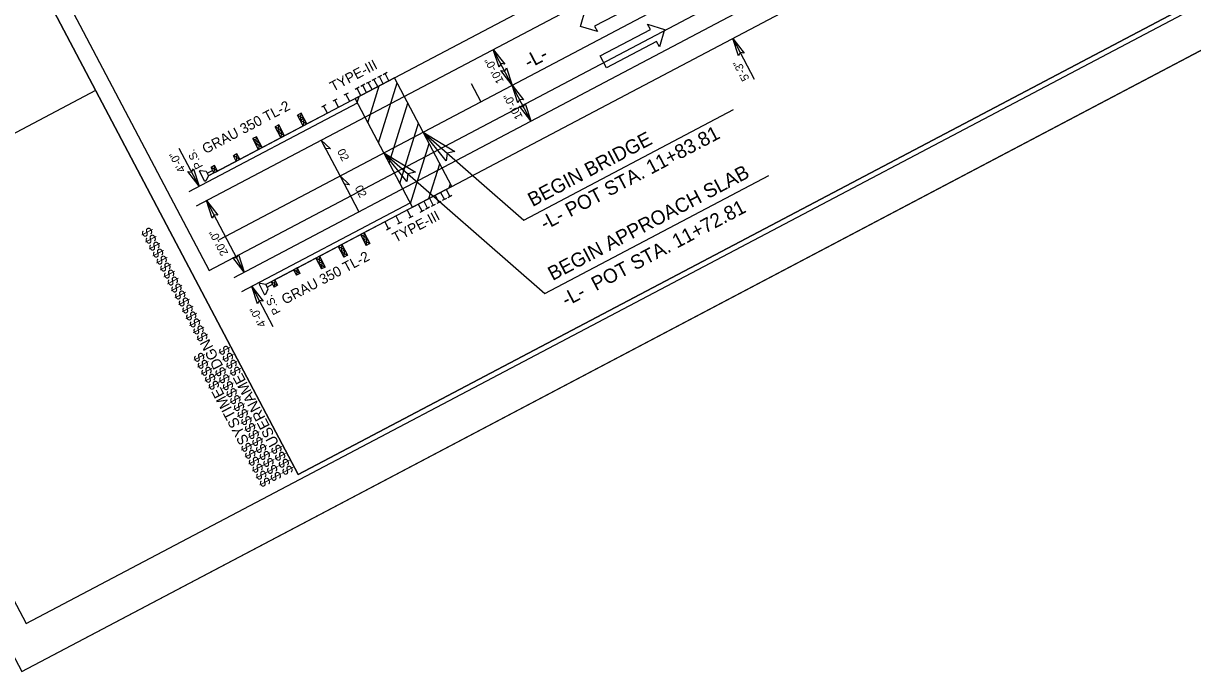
# Model space of a CAD drawing. Extents: x 1380651 to 1383136, y 594581 to 596344.
# Drawn here: x 1381162 to 1381741, y 594581 to 594902 of the extents above; entities that cross this region are included whole.
import ezdxf

# ---------------------------------------------------------------- set-up
doc = ezdxf.new("R2010")
doc.units = 0
for name, color, linetype in [('Default', 7, 'Continuous'), ('Prop Approach Slab', 7, 'Continuous'), ('Prop Approach Slab Hatching', 7, 'Continuous'), ('Prop DGN Element Guardrail', 7, 'Continuous'), ('Prop Dimension', 7, 'Continuous'), ('Prop EOT', 7, 'Continuous'), ('Prop Guardrail', 7, 'Continuous'), ('Prop Guardrail Anchor Unit CELL', 7, 'Continuous'), ('Prop Horizontal Alignment', 7, 'Continuous'), ('Prop Horizontal Alignment Direction Label', 7, 'Continuous'), ('Prop Horizontal Alignment Station Label', 7, 'Continuous'), ('Prop Horizontal Alignment Tick Small', 7, 'Continuous'), ('Prop Lane Arrow CELL', 7, 'Continuous'), ('Prop Paved Shoulder', 7, 'Continuous'), ('Prop Roadway Bridge', 7, 'Continuous'), ('Prop Structure Anchor Unit CELL', 7, 'Continuous'), ('Prop Superelevation  Arrow CELL', 7, 'Continuous'), ('Prop Superelevation Label', 7, 'Continuous'), ('Prop Terminator CELL', 7, 'Continuous'), ('Sheet Block Revision CELL', 7, 'Continuous'), ('Sheet Clip Boundary CELL', 7, 'Continuous'), ('Sheet Cutting Line CELL', 7, 'Continuous'), ('Sheet Layout Plan Border', 7, 'Continuous'), ('Sheet Plan CELL', 7, 'Continuous'), ('Sheet Plot Border Inside CELL', 7, 'Continuous'), ('Sheet Plot Border Outside CELL', 7, 'Continuous')]:
    doc.layers.add(name, color=color, linetype=linetype)

msp = doc.modelspace()

# ---------------------------------------------------------------- linework, layer by layer
at = {"layer": 'Prop Approach Slab'}
for p, q in [((1381326.36, 594865.15), (1381345.82, 594875.41)), ((1381374.19, 594821.59), (1381345.82, 594875.41)), ((1381354.73, 594811.34), (1381326.36, 594865.15)), ((1381354.73, 594811.34), (1381374.19, 594821.59))]:
    msp.add_line(p, q, dxfattribs=at)
at = {"layer": 'Prop Approach Slab Hatching'}
for p, q in [((1381332.67, 594853.18), (1381338.32, 594871.46)), ((1381337.94, 594843.18), (1381347.15, 594872.9)), ((1381327.39, 594863.19), (1381328.32, 594866.18)), ((1381343.22, 594833.17), (1381352.42, 594862.89)), ((1381348.5, 594823.16), (1381357.7, 594852.88)), ((1381353.77, 594813.15), (1381362.97, 594842.87)), ((1381362.92, 594815.65), (1381368.25, 594832.87)), ((1381372.93, 594820.93), (1381373.53, 594822.86))]:
    msp.add_line(p, q, dxfattribs=at)
at = {"layer": 'Prop DGN Element Guardrail'}
for p, q in [((1381345.82, 594875.41), (1381312.65, 594857.92)), ((1381312.65, 594857.92), (1381253.86, 594826.96)), ((1381374.19, 594821.59), (1381341.02, 594804.11)), ((1381341.02, 594804.11), (1381285.73, 594774.96))]:
    msp.add_line(p, q, dxfattribs=at)
at = {"layer": 'Prop Dimension'}
for p, q in [((1381513.25, 594894.91), (1381523.89, 594874.72)), ((1381413.4, 594854.04), (1381394.75, 594889.43)), ((1381249.16, 594821.72), (1381239.33, 594840.36)), ((1381271.54, 594779.26), (1381252.89, 594814.64)), ((1381275.27, 594772.18), (1381285.73, 594752.34))]:
    msp.add_line(p, q, dxfattribs=at)
at = {"layer": 'Prop EOT'}
for p, q in [((1381247.91, 594812.01), (1381655.59, 595026.94)), ((1381266.56, 594776.63), (1381674.25, 594991.56))]:
    msp.add_line(p, q, dxfattribs=at)
at = {"layer": 'Prop Guardrail'}
for p, q in [((1381312.65, 594857.92), (1381301.59, 594852.09)), ((1381341.02, 594804.11), (1381329.96, 594798.28))]:
    msp.add_line(p, q, dxfattribs=at)
at = {"layer": 'Prop Guardrail Anchor Unit CELL'}
for p, q in [((1381299.65, 594857.93), (1381297.88, 594856.99)), ((1381300.71, 594851.62), (1381297.88, 594856.99)), ((1381297.88, 594856.99), (1381301.06, 594855.24)), ((1381299.29, 594854.31), (1381299.65, 594857.93)), ((1381302.48, 594852.56), (1381299.65, 594857.93)), ((1381257.36, 594828.77), (1381301.59, 594852.09)), ((1381288.59, 594852.1), (1381286.82, 594851.17)), ((1381289.65, 594845.79), (1381286.82, 594851.17)), ((1381286.82, 594851.17), (1381290, 594849.41)), ((1381288.23, 594848.48), (1381288.59, 594852.1)), ((1381291.42, 594846.73), (1381288.59, 594852.1)), ((1381301.06, 594855.24), (1381299.29, 594854.31)), ((1381302.48, 594852.56), (1381299.29, 594854.31)), ((1381301.06, 594855.24), (1381300.71, 594851.62)), ((1381302.48, 594852.56), (1381300.71, 594851.62)), ((1381277.53, 594846.27), (1381275.76, 594845.34)), ((1381278.59, 594839.97), (1381275.76, 594845.34)), ((1381275.76, 594845.34), (1381278.94, 594843.58)), ((1381277.18, 594842.65), (1381277.53, 594846.27)), ((1381280.36, 594840.9), (1381277.53, 594846.27)), ((1381290, 594849.41), (1381288.23, 594848.48)), ((1381291.42, 594846.73), (1381288.23, 594848.48)), ((1381290, 594849.41), (1381289.65, 594845.79)), ((1381291.42, 594846.73), (1381289.65, 594845.79)), ((1381278.94, 594843.58), (1381277.18, 594842.65)), ((1381280.36, 594840.9), (1381277.18, 594842.65)), ((1381278.94, 594843.58), (1381278.59, 594839.97)), ((1381280.36, 594840.9), (1381278.59, 594839.97)), ((1381267.89, 594837.76), (1381266.12, 594836.82)), ((1381267.53, 594834.14), (1381266.12, 594836.82)), ((1381269.3, 594835.07), (1381266.12, 594836.82)), ((1381267.89, 594837.75), (1381267.53, 594834.14)), ((1381269.3, 594835.07), (1381267.53, 594834.14)), ((1381269.3, 594835.07), (1381267.89, 594837.76)), ((1381249.85, 594829.54), (1381249.3, 594829.26)), ((1381252.04, 594824.05), (1381249.3, 594829.26)), ((1381249.85, 594829.54), (1381252.72, 594829.12)), ((1381252.72, 594829.12), (1381253.86, 594826.96)), ((1381253.19, 594828.23), (1381255.8, 594829.6)), ((1381256.47, 594828.32), (1381253.86, 594826.96)), ((1381256.83, 594831.93), (1381255.06, 594830.99)), ((1381256.48, 594828.31), (1381255.06, 594830.99)), ((1381258.25, 594829.24), (1381255.06, 594830.99)), ((1381256.83, 594831.93), (1381256.48, 594828.31)), ((1381258.25, 594829.24), (1381256.48, 594828.31)), ((1381258.25, 594829.24), (1381256.83, 594831.93)), ((1381252.58, 594824.34), (1381252.04, 594824.05)), ((1381253.86, 594826.96), (1381252.58, 594824.34)), ((1381285.73, 594774.96), (1381329.96, 594798.28)), ((1381330.85, 594798.74), (1381329.08, 594797.81)), ((1381330.85, 594798.74), (1381330.49, 594795.12)), ((1381330.85, 594798.74), (1381333.68, 594793.37)), ((1381319.79, 594792.91), (1381318.02, 594791.98)), ((1381319.79, 594792.91), (1381319.43, 594789.3)), ((1381319.79, 594792.91), (1381322.62, 594787.54)), ((1381329.08, 594797.81), (1381331.91, 594792.44)), ((1381332.26, 594796.06), (1381329.08, 594797.81)), ((1381332.26, 594796.06), (1381330.49, 594795.12)), ((1381330.49, 594795.12), (1381333.68, 594793.37)), ((1381331.91, 594792.44), (1381332.26, 594796.06)), ((1381333.68, 594793.37), (1381331.91, 594792.44)), ((1381308.73, 594787.09), (1381306.96, 594786.15)), ((1381308.73, 594787.09), (1381308.38, 594783.47)), ((1381308.73, 594787.09), (1381311.56, 594781.71)), ((1381318.02, 594791.98), (1381320.85, 594786.61)), ((1381321.2, 594790.23), (1381318.02, 594791.98)), ((1381321.2, 594790.23), (1381319.43, 594789.3)), ((1381319.43, 594789.3), (1381322.62, 594787.54)), ((1381320.85, 594786.61), (1381321.2, 594790.23)), ((1381322.62, 594787.54), (1381320.85, 594786.61)), ((1381297.67, 594781.26), (1381295.9, 594780.32)), ((1381297.67, 594781.26), (1381297.32, 594777.64)), ((1381297.67, 594781.26), (1381299.09, 594778.57)), ((1381306.96, 594786.15), (1381309.79, 594780.78)), ((1381310.15, 594784.4), (1381306.96, 594786.15)), ((1381310.15, 594784.4), (1381308.38, 594783.47)), ((1381308.38, 594783.47), (1381311.56, 594781.71)), ((1381309.79, 594780.78), (1381310.15, 594784.4)), ((1381311.56, 594781.71), (1381309.79, 594780.78)), ((1381286.62, 594775.43), (1381284.85, 594774.49)), ((1381286.62, 594775.43), (1381286.26, 594771.81)), ((1381286.62, 594775.43), (1381288.03, 594772.74)), ((1381295.9, 594780.32), (1381297.32, 594777.64)), ((1381299.09, 594778.57), (1381295.9, 594780.32)), ((1381299.09, 594778.57), (1381297.32, 594777.64)), ((1381279.37, 594773.52), (1381278.83, 594773.23)), ((1381278.83, 594773.23), (1381281.58, 594768.04)), ((1381282.26, 594773.1), (1381279.37, 594773.52)), ((1381282.12, 594768.32), (1381283.4, 594770.93)), ((1381284.86, 594774.48), (1381282.26, 594773.1)), ((1381283.4, 594770.93), (1381282.26, 594773.1)), ((1381282.93, 594771.83), (1381285.53, 594773.2)), ((1381284.85, 594774.49), (1381286.26, 594771.81)), ((1381288.03, 594772.74), (1381284.85, 594774.49)), ((1381288.03, 594772.74), (1381286.26, 594771.81)), ((1381282.12, 594768.32), (1381281.58, 594768.04))]:
    msp.add_line(p, q, dxfattribs=at)
at = {"layer": 'Prop Horizontal Alignment'}
msp.add_line((1381259.34, 594795.43), (1381664.92, 595009.25), dxfattribs=at)
at = {"layer": 'Prop Horizontal Alignment Station Label'}
for p, q in [((1381409.83, 594805), (1381513.58, 594859.7)), ((1381360.01, 594848.5), (1381409.83, 594805)), ((1381340.55, 594838.24), (1381420.3, 594768.6)), ((1381420.3, 594768.6), (1381531.04, 594826.98))]:
    msp.add_line(p, q, dxfattribs=at)
at = {"layer": 'Prop Horizontal Alignment Tick Small'}
msp.add_line((1381388.65, 594863.6), (1381383.99, 594872.45), dxfattribs=at)
at = {"layer": 'Prop Lane Arrow CELL'}
for p, q in [((1381469.66, 594913.99), (1381444.89, 594900.93)), ((1381437.82, 594900.82), (1381440.41, 594909.42)), ((1381446.29, 594898.28), (1381437.82, 594900.82)), ((1381444.89, 594900.93), (1381446.29, 594898.28)), ((1381447.7, 594886.21), (1381472.47, 594899.27)), ((1381472.47, 594899.27), (1381471.07, 594901.92)), ((1381471.07, 594901.92), (1381479.54, 594899.38)), ((1381479.54, 594899.38), (1381476.95, 594890.78)), ((1381475.55, 594893.43), (1381450.78, 594880.37)), ((1381476.95, 594890.78), (1381475.55, 594893.43)), ((1381450.78, 594880.37), (1381447.7, 594886.21))]:
    msp.add_line(p, q, dxfattribs=at)
at = {"layer": 'Prop Paved Shoulder'}
for p, q in [((1381244.18, 594819.09), (1381327.49, 594863.01)), ((1381270.29, 594769.55), (1381353.6, 594813.47))]:
    msp.add_line(p, q, dxfattribs=at)
at = {"layer": 'Prop Roadway Bridge'}
for p, q in [((1381345.82, 594875.41), (1381518.11, 594966.23)), ((1381374.19, 594821.59), (1381546.48, 594912.42))]:
    msp.add_line(p, q, dxfattribs=at)
at = {"layer": 'Prop Structure Anchor Unit CELL'}
for p, q in [((1381345.82, 594875.41), (1381312.65, 594857.92)), ((1381333.91, 594873.65), (1381331.89, 594872.58)), ((1381336.68, 594875.11), (1381334.65, 594874.04)), ((1381337.53, 594871.04), (1381335.66, 594874.57)), ((1381339.44, 594876.57), (1381337.41, 594875.5)), ((1381340.29, 594872.49), (1381338.43, 594876.03)), ((1381342.2, 594878.02), (1381340.18, 594876.95)), ((1381343.06, 594873.95), (1381341.19, 594877.49)), ((1381322.85, 594867.82), (1381320.83, 594866.75)), ((1381328.38, 594870.74), (1381326.36, 594869.67)), ((1381329.24, 594866.66), (1381327.37, 594870.2)), ((1381331.15, 594872.19), (1381329.12, 594871.13)), ((1381332, 594868.12), (1381330.13, 594871.66)), ((1381334.76, 594869.58), (1381332.9, 594873.12)), ((1381311.8, 594861.99), (1381309.77, 594860.92)), ((1381317.33, 594864.91), (1381315.3, 594863.84)), ((1381318.18, 594860.83), (1381316.31, 594864.37)), ((1381323.71, 594863.75), (1381321.84, 594867.29)), ((1381312.65, 594857.92), (1381310.78, 594861.46)), ((1381374.19, 594821.59), (1381341.02, 594804.11)), ((1381363.13, 594815.77), (1381365, 594812.23)), ((1381365.9, 594817.22), (1381367.76, 594813.68)), ((1381368.66, 594818.68), (1381370.53, 594815.14)), ((1381371.54, 594815.68), (1381369.51, 594814.61)), ((1381371.43, 594820.14), (1381373.29, 594816.6)), ((1381374.31, 594817.13), (1381372.28, 594816.06)), ((1381352.08, 594809.94), (1381353.94, 594806.4)), ((1381357.6, 594812.85), (1381359.47, 594809.31)), ((1381360.48, 594809.85), (1381358.46, 594808.78)), ((1381360.37, 594814.31), (1381362.23, 594810.77)), ((1381363.25, 594811.3), (1381361.22, 594810.24)), ((1381366.01, 594812.76), (1381363.99, 594811.69)), ((1381368.78, 594814.22), (1381366.75, 594813.15)), ((1381341.02, 594804.11), (1381342.88, 594800.57)), ((1381346.55, 594807.02), (1381348.41, 594803.48)), ((1381349.43, 594804.02), (1381347.4, 594802.95)), ((1381354.95, 594806.93), (1381352.93, 594805.86)), ((1381343.9, 594801.1), (1381341.87, 594800.03))]:
    msp.add_line(p, q, dxfattribs=at)
at = {"layer": 'Prop Superelevation  Arrow CELL'}
for points in [[(1381309.62, 594844.55), (1381314.19, 594840.17), (1381311.77, 594840.46)], [(1381318.94, 594826.85), (1381323.51, 594822.48), (1381321.1, 594822.76)]]:
    msp.add_lwpolyline(points, close=True, dxfattribs=at)
at = {"layer": 'Prop Superelevation Label'}
for p, q in [((1381318.94, 594826.85), (1381309.62, 594844.55)), ((1381328.27, 594809.16), (1381318.94, 594826.85))]:
    msp.add_line(p, q, dxfattribs=at)
at = {"layer": 'Prop Terminator CELL'}
for points in [[(1381516.08, 594886.22), (1381513.25, 594894.91), (1381518.89, 594887.65), (1381516.94, 594887.92)], [(1381397.58, 594880.74), (1381394.75, 594889.43), (1381400.39, 594882.17), (1381398.43, 594882.44)], [(1381401.25, 594880.42), (1381404.08, 594871.74), (1381398.44, 594878.99), (1381400.39, 594878.72)], [(1381406.9, 594863.05), (1381404.08, 594871.74), (1381409.71, 594864.48), (1381407.76, 594864.75)], [(1381410.58, 594862.73), (1381413.4, 594854.04), (1381407.77, 594861.3), (1381409.72, 594861.03)], [(1381371.5, 594834.31), (1381360.01, 594848.5), (1381375.73, 594838.98), (1381371.89, 594838.09)], [(1381352.04, 594824.05), (1381340.55, 594838.24), (1381356.27, 594828.72), (1381352.43, 594827.83)], [(1381246.33, 594830.4), (1381249.16, 594821.72), (1381243.52, 594828.98), (1381245.47, 594828.7)], [(1381255.71, 594805.95), (1381252.89, 594814.64), (1381258.52, 594807.38), (1381256.57, 594807.65)], [(1381268.72, 594787.94), (1381271.54, 594779.26), (1381265.91, 594786.51), (1381267.86, 594786.24)], [(1381278.1, 594763.49), (1381275.27, 594772.18), (1381280.91, 594764.92), (1381278.96, 594765.19)]]:
    msp.add_lwpolyline(points, close=True, dxfattribs=at)
at = {"layer": 'Sheet Block Revision CELL'}
msp.add_lwpolyline([(1381144.43, 594840.95), (1380775.71, 595540.36), (1380829.25, 595568.61), (1381197.97, 594869.2)], close=True, dxfattribs=at)
at = {"layer": 'Sheet Clip Boundary CELL'}
msp.add_lwpolyline([(1381254.23, 594780.01), (1382566.26, 595471.7), (1382154.39, 596252.97), (1381978.55, 596160.27), (1381909.21, 596291.79), (1380773.01, 595692.8)], close=True, dxfattribs=at)
at = {"layer": 'Sheet Cutting Line CELL'}
msp.add_line((1381161.45, 594581.45), (1382650.68, 595366.55), dxfattribs=at)
at = {"layer": 'Sheet Layout Plan Border'}
msp.add_lwpolyline([(1381298.21, 594679), (1382625.14, 595378.54), (1382205.45, 596174.64), (1382028.49, 596081.35), (1381958.53, 596214.06), (1380808.55, 595607.8)], close=True, dxfattribs=at)
at = {"layer": 'Sheet Plan CELL'}
msp.add_line((1381298.23, 594679.01), (1381298.23, 594679.01), dxfattribs=at)
for points in [[(1382135.49, 596307.38), (1380808.56, 595607.84), (1381298.23, 594679.01), (1382625.14, 595378.54)], [(1381298.23, 594679.01), (1380808.55, 595607.8), (1381958.5, 596214.09), (1382028.49, 596081.35), (1382205.45, 596174.63), (1382625.14, 595378.54)]]:
    msp.add_lwpolyline(points, close=True, dxfattribs=at)
at = {"layer": 'Sheet Plot Border Inside CELL'}
msp.add_lwpolyline([(1381163.62, 594605.21), (1382637.35, 595382.15), (1382145.37, 596315.4), (1380671.62, 595538.46)], close=True, dxfattribs=at)
at = {"layer": 'Sheet Plot Border Outside CELL'}
msp.add_lwpolyline([(1381161.45, 594581.45), (1382650.68, 595366.55), (1382140.02, 596335.19), (1380650.8, 595550.09)], close=True, dxfattribs=at)

# ---------------------------------------------------------------- texts
at = {"layer": 'Default'}
for p in [(1381251.21, 594831.5), (1381289.67, 594759.42)]:
    msp.add_text('P.S.', height=4, rotation=117.7977, dxfattribs=at).set_placement(p)
at = {"layer": 'Prop Dimension'}
for s, p in [('10\'-0"', (1381400.1, 594873.78)), ('5\'-3"', (1381521.61, 594875.04)), ('10\'-0"', (1381409.43, 594856.08)), ('4\'-0"', (1381242.66, 594829.76)), ('20\'-0"', (1381263.74, 594788.57)), ('4\'-0"', (1381282.49, 594753.15))]:
    msp.add_text(s, height=4, rotation=117.7977, dxfattribs=at).set_placement(p)
at = {"layer": 'Prop Guardrail Anchor Unit CELL'}
for p in [(1381252.32, 594837.59), (1381291.61, 594763.06)]:
    msp.add_text('GRAU 350 TL-2', height=5, rotation=27.7977, dxfattribs=at).set_placement(p)
at = {"layer": 'Prop Horizontal Alignment Direction Label'}
msp.add_text('-L-', height=7, rotation=27.7977, dxfattribs=at).set_placement((1381412.32, 594879.73))
at = {"layer": 'Prop Horizontal Alignment Station Label'}
for s, p in [('-L- POT STA. 11+83.81', (1381420.29, 594799.79)), ('BEGIN BRIDGE', (1381414.17, 594811.41)), ('BEGIN APPROACH SLAB', (1381424.1, 594774.81)), ('-L-  POT STA. 11+72.81', (1381430.86, 594761.98))]:
    msp.add_text(s, height=7, rotation=27.7977, dxfattribs=at).set_placement(p)
at = {"layer": 'Prop Structure Anchor Unit CELL'}
for p in [(1381315.52, 594868.43), (1381346.43, 594793.71)]:
    msp.add_text('TYPE-III', height=5, rotation=27.7977, dxfattribs=at).set_placement(p)
at = {"layer": 'Prop Superelevation Label'}
for p in [(1381317.33, 594839), (1381326.06, 594820.92)]:
    msp.add_text('02', height=4, rotation=297.7977, dxfattribs=at).set_placement(p)
at = {"layer": 'Sheet Plan CELL'}
for s, p in [('$$$$$$$$$$$$$$$$DGN$$$$$$$$$$$$$$$$', (1381290.37, 594677.54)), ('$$$$USERNAME$$$$', (1381296.16, 594680.6)), ('$$$$$$SYSTIME$$$$$', (1381285.01, 594674.68))]:
    msp.add_text(s, height=5.25, rotation=117.7977, dxfattribs=at).set_placement(p)

doc.saveas('drawing.dxf')
